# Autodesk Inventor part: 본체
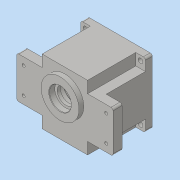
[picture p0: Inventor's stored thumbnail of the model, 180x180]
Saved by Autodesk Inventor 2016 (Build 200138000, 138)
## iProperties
Created: 2020-08
Part Number: 본체
Material: 일반
Document SubType Name: Modeling
Designer: User
Density: 1 g/cm^3
Appearance: 기본값
Author: User
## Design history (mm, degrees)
sketch "스케치1"
  geometry: L1 (-33, 47)-(33, 47); L2 (33, 47)-(33, -47); L3 (33, -47)-(-33, -47); L4 (-33, -47)-(-33, 47); L5 (-33, 47)-(33, -47); L6 (33, 47)-(-33, -47); L7 (-70, 30)-(70, 30); L8 (70, 30)-(70, -30); L9 (70, -30)-(-70, -30); L10 (-70, -30)-(-70, 30); L11 (-70, 30)-(70, -30); L12 (70, 30)-(-70, -30); 1 further point
  constraints: 24 end point, 4 midpoint, 4 parallel, 2 horizontal, 2 perpendicular
  dimensions: "d0" = 66 distance of L2.end L3.end; "d1" = 94 distance of L1.end L2.end; "d2" = 140 distance of L8.end L9.end; "d3" = 60 distance of L7.end L8.end
extrude "돌출1" new body sketch "스케치1" distance "d4" = 13; taper "d5" = 0 deg
sketch "스케치2"
  geometry: L1 (-47, 47)-(47, 47); L2 (47, 47)-(47, -47); L3 (47, -47)-(-47, -47); L4 (-47, -47)-(-47, 47); L5 (-47, 47)-(47, -47); L6 (47, 47)-(-47, -47); 1 further point
  constraints: 12 end point, 2 midpoint, 2 parallel, 1 horizontal, 1 perpendicular
  dimensions: "d6" = 94 distance of L2.end L3.end; "d7" = 94 distance of L1.end L2.end
extrude "돌출2" join sketch "스케치2" distance "d8" = 67; taper "d9" = 0 deg
sketch "스케치3"
  geometry: L1 (-47, 30)-(-33, 30) reference; L2 (-33, 30)-(-33, 47) reference; L3 (-33, 47)-(-47, 47) reference; L4 (-47, 47)-(-47, 30) reference; L5 (-33, -47)-(-33, -30) reference; L6 (-33, -30)-(-47, -30) reference; L7 (-47, -30)-(-47, -47) reference; L8 (-47, -47)-(-33, -47) reference; L9 (33, -30)-(33, -47) reference; L10 (33, -47)-(47, -47) reference; L11 (47, -47)-(47, -30) reference; L12 (47, -30)-(33, -30) reference; L13 (33, 30)-(47, 30) reference; L14 (47, 30)-(47, 47) reference; L15 (47, 47)-(33, 47) reference; L16 (33, 47)-(33, 30) reference; 1 further point
extrude "돌출3" cut sketch "스케치3" distance "d10" = 57; taper "d11" = 0 deg
sketch "스케치4"
  geometry: C1 r 27.5 at (0, 11); 1 further point
  constraints: 1 centre point, 1 vertical alignment
  dimensions: "d12" = 55 diameter of C1; "d13" = 11 distance of point (0, 0) C1.centre
extrude "돌출4" join sketch "스케치4" distance "d14" = 7; taper "d15" = 0 deg
sketch "스케치5"
  geometry: C1 r 16 at (0, 0); C2 r 27.5 at (0, 0) reference; 1 further point
  constraints: 1 centre point, 1 concentric
  dimensions: "d16" = 32 diameter of C1
extrude "돌출5" cut sketch "스케치5" distance "d17" = 8.3; taper "d18" = 0 deg
sketch "스케치6"
  geometry: C1 r 12.5 at (0, 0); C2 r 16 at (0, 0) reference; 1 further point
  constraints: 1 centre point, 1 concentric
  dimensions: "d19" = 25 diameter of C1
extrude "돌출6" cut sketch "스케치6" distance "d20" = 4.7; taper "d21" = 0 deg
sketch "스케치7"
  geometry: C1 r 43 at (0, 0); 1 further point
  constraints: 1 centre point, 1 coincident
  dimensions: "d22" = 86 diameter of C1
extrude "돌출7" cut sketch "스케치7" distance "d23" = 9; taper "d24" = 0 deg
sketch "스케치8"
  geometry: C1 r 40 at (0, 0); C2 r 43 at (0, 0) reference; 1 further point
  constraints: 1 centre point, 1 concentric
  dimensions: "d25" = 80 diameter of C1
extrude "돌출8" cut sketch "스케치8" distance "d26" = 71; taper "d27" = 0 deg
sketch "스케치9"
  geometry: C1 r 27.5 at (0, 11) reference; C2 r 21 at (0, 11); C3 r 15 at (0, -20); 1 further point
  constraints: 2 centre point, 1 coincident, 1 vertical alignment
  dimensions: "d28" = 21 radius of C2; "d29" = 15 radius of C3; "d30" = 20 distance of point (0, 0) C3.centre
extrude "돌출9" join sketch "스케치9" distance "d31" = 7; taper "d32" = 0 deg
sketch "스케치10"
  geometry: C1 r 17.5 at (0, 11); A1 r 21 centre (0, 11) between (8.978, -7.984) and (-8.978, -7.984) reference; A2 r 21 centre (0, 11) between (8.978, -7.984) and (-8.978, -7.984) reference; A3 r 15 centre (0, -20) between (-8.978, -7.984) and (8.978, -7.984) reference; 1 further point
  constraints: 1 centre point, 1 coincident
  dimensions: "d33" = 35 diameter of C1
extrude "돌출10" cut sketch "스케치10" distance "d34" = 10; taper "d35" = 0 deg
sketch "스케치11"
  geometry: C1 r 11 at (0, -20); A1 r 15 centre (0, -20) between (-8.978, -7.984) and (8.978, -7.984) reference; 1 further point
  constraints: 1 centre point, 1 concentric
  dimensions: "d36" = 22 diameter of C1
extrude "돌출11" cut sketch "스케치11" distance "d37" = 7; taper "d38" = 0 deg
sketch "스케치12"
  geometry: C1 r 9.5 at (0, 0); C2 r 11 at (0, 0) reference; 1 further point
  constraints: 1 centre point, 1 concentric
  dimensions: "d39" = 19 diameter of C1
extrude "돌출12" cut sketch "스케치12" distance "d40" = 3; taper "d41" = 0 deg
sketch "스케치13" dims "d42" = 36
  geometry: A1 r 4 centre (36, 0) between (36.19, 3.995) and (36.19, -3.995); A2 r 3 centre (36.333, 6.992) between (36.19, 3.995) and (39.279, 7.559); A3 r 40 centre (0, 0) between (39.279, -7.559) and (39.279, 7.559) reference; A4 r 3 centre (36.333, -6.992) between (39.279, -7.559) and (36.19, -3.995); 2 further points
  constraints: 8 point on circle, 4 tangent, 3 centre point, 2 horizontal alignment, 1 coincident, 2 other
  dimensions: "d43" = 4 radius of A1; "d44" = 3 radius of A2; "d45" = 3 radius of A4
extrude "돌출13" join sketch "스케치13" distance "d46" = 62; taper "d47" = 0 deg
sketch "스케치14"
  geometry: A1 r 4 centre (36, 0) between (36.19, 3.995) and (36.19, -3.995) reference; 1 further point
hole "구멍1" sketch "스케치14" at (36, 0) diameter "d48" = 3.242; stored, may be unused: countersink angle "d52" = 90 deg, drill point angle "d54" = 118 deg; dims "d49" = 7, "d50" = 4, "d51" = 2, "d53" = 9
sketch "스케치15"
  geometry: 2 further points
  dimensions: "d55" = 60 horizontal distance of point (0, 0) point (-60, 19); "d56" = 19 vertical distance of point (0, 0) point (-60, 19)
hole "구멍2" sketch "스케치15" at (-60, 19) diameter "d57" = 4.5; stored, may be unused: countersink angle "d61" = 90 deg, drill point angle "d63" = 118 deg; dims "d58" = 7, "d59" = 10, "d60" = 5, "d62" = 13
sketch "스케치16"
  geometry: C1 r 3.5 at (-40, 40); 1 further point
  constraints: 1 centre point
  dimensions: "d70" = 7 diameter of C1; "d71" = 40 horizontal distance of point (0, 0) C1.centre; "d72" = 40 horizontal distance of point (0, 0) C1.centre
extrude "돌출14" cut sketch "스케치16" distance "d73" = 62; taper "d74" = 0 deg
fillet "모깎기1" dims "d81" = 3
chamfer "모따기1" distance "d82" = 1; stored, may be unused: second distance "d83" = 2, angle "d84" = 45 deg
chamfer "모따기2" distance "d85" = 0.8; stored, may be unused: second distance "d86" = 2, angle "d87" = 30 deg
chamfer "모따기3" distance "d88" = 1; stored, may be unused: second distance "d89" = 2, angle "d90" = 30 deg
fillet "모깎기2" dims "d91" = 3
fillet "모깎기3" dims "d92" = 3
node "솔리드1"
mirror "대칭1"
pattern_linear "직사각형 패턴1" dims "d66" = 120, "d69" = 38
pattern_linear "직사각형 패턴2" dims "d77" = 80
node "투영된 루프1"
node "투영된 루프2"
node "투영된 루프3"
node "투영된 루프4"
node "투영된 루프5"
